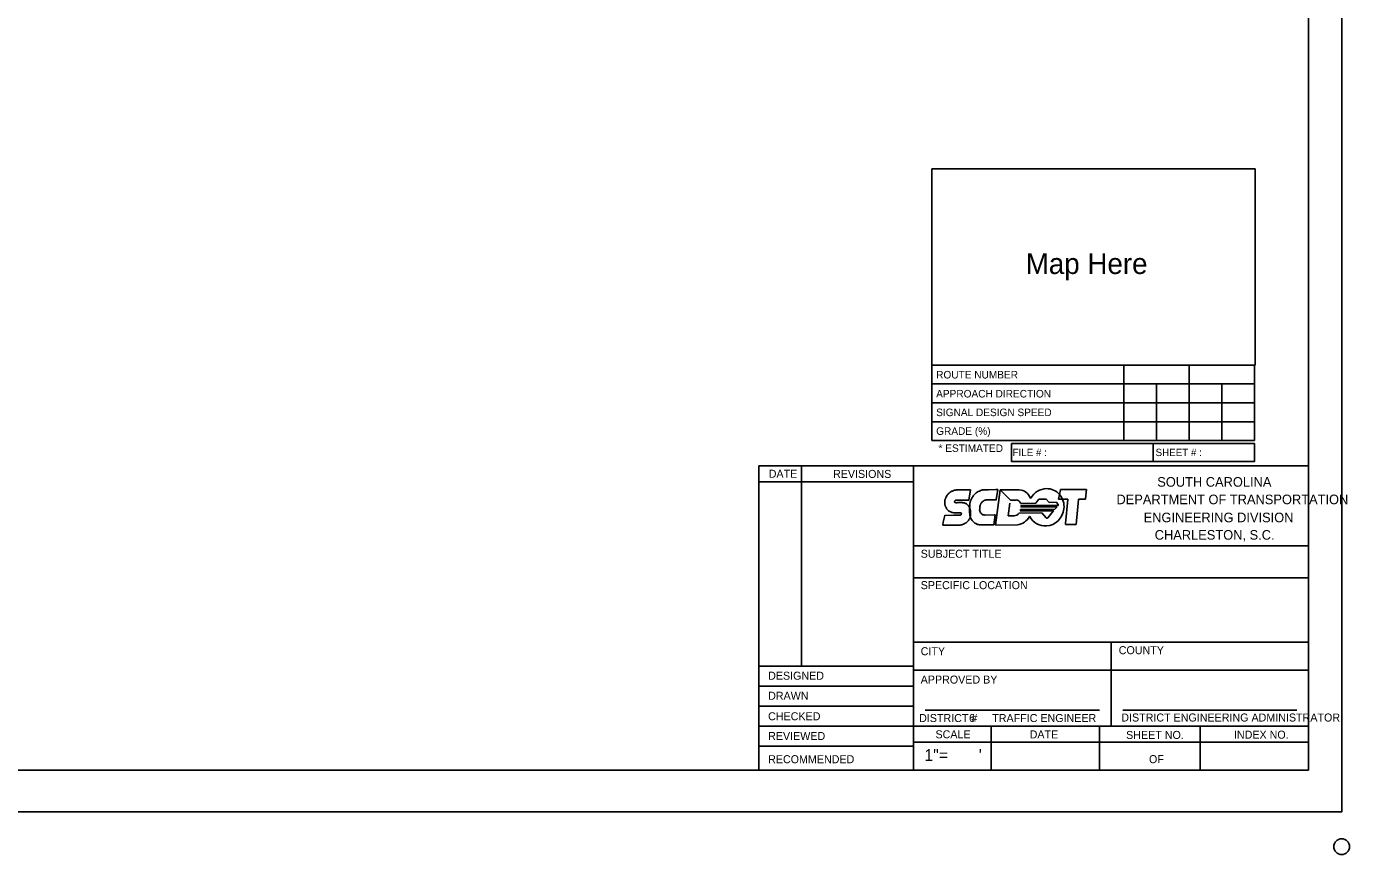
# Model space of a CAD drawing. Extents: x 0 to 3.01, y -0.05 to 1.83.
# Drawn here: x 1.504 to 3.009, y -0.048 to 0.892 of the extents above; entities that cross this region are included whole.
import ezdxf

# ---------------------------------------------------------------- set-up
doc = ezdxf.new("R2010")
doc.units = 0
doc.layers.add('RD_SHT_IplotShp', color=7, linetype='Continuous')
doc.layers.add('TR_TS_Border', color=7, linetype='Continuous')

msp = doc.modelspace()

# ---------------------------------------------------------------- linework, layer by layer
at = {"layer": 'RD_SHT_IplotShp'}
msp.add_lwpolyline([(0, 0), (3, 0), (3, 1.8333), (0, 1.8333)], close=True, dxfattribs=at)
at = {"layer": 'TR_TS_Border'}
for p, q in [((3, 0), (3, 1.8333)), ((2.9623, 0.0475), (2.9623, 1.7754)), ((2.5341, 0.5078), (2.9009, 0.5078)), ((2.5341, 0.422), (2.5341, 0.5078)), ((2.7521, 0.422), (2.7521, 0.5078)), ((2.8265, 0.422), (2.8265, 0.5078)), ((2.9009, 0.422), (2.9009, 0.5078)), ((2.5341, 0.4863), (2.9009, 0.4863)), ((2.7893, 0.422), (2.7893, 0.4863)), ((2.8637, 0.422), (2.8637, 0.4863)), ((2.5341, 0.4649), (2.9009, 0.4649)), ((2.5341, 0.4434), (2.9009, 0.4434)), ((2.5341, 0.422), (2.9009, 0.422)), ((2.7856, 0.4186), (2.7856, 0.3983)), ((2.3372, 0.3932), (2.9623, 0.3932)), ((2.3372, 0.0475), (2.3372, 0.3932)), ((2.3856, 0.3932), (2.3856, 0.1657)), ((2.5133, 0.0475), (2.5133, 0.3932)), ((2.3372, 0.375), (2.5133, 0.375)), ((2.6065, 0.3259), (2.6116, 0.3661)), ((2.6233, 0.3544), (2.6116, 0.3661)), ((2.6116, 0.3661), (2.6334, 0.366)), ((2.6116, 0.3661), (2.6233, 0.3544)), ((2.6802, 0.3659), (2.678, 0.3555)), ((2.6803, 0.3663), (2.6802, 0.3659)), ((2.6809, 0.3664), (2.6804, 0.3664)), ((2.7089, 0.3665), (2.6809, 0.3664)), ((2.7086, 0.3556), (2.7099, 0.3665)), ((2.7096, 0.3665), (2.7089, 0.3665)), ((2.7099, 0.3665), (2.7096, 0.3665)), ((2.6227, 0.3509), (2.6206, 0.3364)), ((2.6298, 0.3544), (2.6233, 0.3544)), ((2.6522, 0.3507), (2.6349, 0.3506)), ((2.6353, 0.348), (2.677, 0.3483)), ((2.6758, 0.3466), (2.6353, 0.3464)), ((2.6557, 0.3554), (2.6522, 0.3507)), ((2.6638, 0.3554), (2.6557, 0.3554)), ((2.6674, 0.3517), (2.6638, 0.3554)), ((2.6753, 0.3518), (2.6674, 0.3517)), ((2.6739, 0.3439), (2.676, 0.3463)), ((2.6757, 0.3517), (2.6777, 0.3493)), ((2.6757, 0.3517), (2.6777, 0.3493)), ((2.6777, 0.3493), (2.6757, 0.3517)), ((2.677, 0.3483), (2.6771, 0.3478)), ((2.6771, 0.3478), (2.6772, 0.3477)), ((2.6772, 0.3477), (2.6777, 0.3487)), ((2.678, 0.3555), (2.6882, 0.3554)), ((2.6886, 0.3549), (2.686, 0.3278)), ((2.6982, 0.3265), (2.7008, 0.3549)), ((2.7012, 0.3554), (2.7083, 0.3554)), ((2.6206, 0.3364), (2.6274, 0.3366)), ((2.633, 0.3395), (2.659, 0.3397)), ((2.672, 0.3422), (2.6345, 0.342)), ((2.6349, 0.3437), (2.6739, 0.3439)), ((2.659, 0.3397), (2.6641, 0.3342)), ((2.6659, 0.3342), (2.6721, 0.3418)), ((2.6313, 0.3261), (2.6065, 0.3259)), ((2.686, 0.3278), (2.686, 0.327)), ((2.6863, 0.3265), (2.6982, 0.3265)), ((2.9623, 0.3022), (2.5133, 0.3022)), ((2.9623, 0.2658), (2.5133, 0.2658)), ((2.9623, 0.193), (2.5133, 0.193)), ((2.7378, 0.193), (2.7378, 0.0975)), ((2.3372, 0.1657), (2.5133, 0.1657)), ((2.9623, 0.1612), (2.5133, 0.1612)), ((2.3372, 0.143), (2.5133, 0.143)), ((2.3372, 0.1203), (2.5133, 0.1203)), ((2.5265, 0.1157), (2.7246, 0.1157)), ((2.9491, 0.1157), (2.751, 0.1157)), ((2.9623, 0.0975), (2.3372, 0.0975)), ((2.6013, 0.0475), (2.6013, 0.0975)), ((2.7246, 0.0475), (2.7246, 0.0975)), ((2.8391, 0.0475), (2.8391, 0.0975)), ((2.9623, 0.0793), (2.5133, 0.0793)), ((2.3372, 0.0748), (2.5133, 0.0748)), ((0.1686, 0.0475), (2.9623, 0.0475)), ((0.0238, 0), (3, 0))]:
    msp.add_line(p, q, dxfattribs=at)
for points in [[(2.5341, 0.5078), (2.9015, 0.5078), (2.9015, 0.7306), (2.5341, 0.7306)], [(2.6244, 0.4186), (2.9009, 0.4186), (2.9009, 0.3983), (2.6244, 0.3983)]]:
    msp.add_lwpolyline(points, close=True, dxfattribs=at)
for points in [[(2.5561, 0.3406), (2.5554, 0.341), (2.5545, 0.3413), (2.5537, 0.3417), (2.553, 0.3422), (2.5523, 0.3428), (2.5517, 0.3434), (2.5512, 0.3438), (2.5507, 0.3445), (2.5505, 0.3452), (2.5501, 0.3459), (2.5496, 0.3466), (2.5494, 0.3473), (2.5491, 0.3479), (2.549, 0.3485), (2.5489, 0.3491), (2.5488, 0.3495), (2.5488, 0.3502), (2.5488, 0.3515), (2.5488, 0.3522), (2.5488, 0.3533), (2.5489, 0.3542), (2.549, 0.3549), (2.5493, 0.3558), (2.5497, 0.3566), (2.55, 0.3574), (2.5505, 0.3583), (2.5507, 0.3589), (2.5513, 0.3599), (2.552, 0.3606), (2.5527, 0.3615), (2.5535, 0.3623), (2.5542, 0.3627), (2.555, 0.3634), (2.5561, 0.364), (2.5566, 0.3643), (2.5575, 0.3646), (2.5581, 0.3649), (2.5587, 0.3652), (2.5596, 0.3655), (2.5605, 0.3656), (2.5613, 0.3657), (2.5621, 0.3658), (2.5627, 0.3658), (2.5634, 0.3658), (2.5725, 0.3659), (2.5778, 0.3659)], [(2.5778, 0.3659), (2.5759, 0.3543), (2.562, 0.3543), (2.5616, 0.3542), (2.561, 0.3541), (2.5608, 0.3539), (2.5605, 0.3537), (2.5602, 0.3535), (2.5601, 0.3534), (2.5601, 0.3532), (2.56, 0.3529), (2.5599, 0.3526), (2.5599, 0.3524), (2.5599, 0.3521), (2.56, 0.3521), (2.5601, 0.3517), (2.5602, 0.3516), (2.5604, 0.3515), (2.5608, 0.3514), (2.5609, 0.3514), (2.5614, 0.3513), (2.5624, 0.3513), (2.5634, 0.3514), (2.5641, 0.3514), (2.565, 0.3515), (2.5676, 0.3515)], [(2.5774, 0.3517), (2.5773, 0.3509), (2.5771, 0.35), (2.577, 0.3488), (2.577, 0.348), (2.577, 0.3471), (2.577, 0.3468), (2.5769, 0.3464), (2.5769, 0.3462), (2.5768, 0.3458), (2.5768, 0.3453), (2.5768, 0.345), (2.5767, 0.3446), (2.5767, 0.344), (2.5767, 0.3435), (2.5767, 0.3431), (2.5767, 0.3426), (2.5767, 0.3423), (2.5767, 0.3419), (2.5767, 0.3413), (2.5768, 0.3405), (2.5769, 0.3397), (2.577, 0.339), (2.577, 0.3383), (2.5771, 0.3375), (2.5773, 0.337), (2.5773, 0.3364), (2.5774, 0.3359), (2.5777, 0.3352), (2.5778, 0.3345), (2.5779, 0.3341), (2.5785, 0.3332), (2.579, 0.3324), (2.5793, 0.3318), (2.5798, 0.3312), (2.5803, 0.3306), (2.581, 0.3299), (2.5816, 0.3293), (2.5822, 0.3288), (2.5829, 0.3282), (2.5839, 0.3278), (2.5847, 0.3272), (2.5853, 0.327), (2.586, 0.3267), (2.5866, 0.3266), (2.5871, 0.3264), (2.588, 0.3262), (2.5884, 0.3262), (2.5891, 0.3261), (2.5896, 0.3261), (2.6042, 0.3261), (2.6043, 0.3262), (2.6043, 0.3262), (2.6058, 0.3374), (2.6053, 0.3374), (2.5945, 0.3373), (2.5935, 0.3374), (2.5927, 0.3375), (2.592, 0.3377), (2.5913, 0.3381), (2.5907, 0.3385), (2.59, 0.3392), (2.5895, 0.3398), (2.5891, 0.3403), (2.5888, 0.341), (2.5886, 0.3416), (2.5884, 0.3422), (2.5883, 0.3431), (2.5884, 0.3442), (2.5885, 0.3452), (2.5886, 0.3464), (2.5887, 0.3472), (2.5888, 0.3483), (2.5891, 0.349), (2.5895, 0.3497), (2.5898, 0.3505), (2.5903, 0.3513), (2.591, 0.3518), (2.5916, 0.3525), (2.5922, 0.3531), (2.5932, 0.3536), (2.594, 0.3541), (2.5947, 0.3543), (2.5951, 0.3544), (2.5959, 0.3545), (2.5968, 0.3545), (2.6072, 0.3545), (2.6073, 0.3546), (2.6089, 0.3665)], [(2.6089, 0.3665), (2.6067, 0.3665), (2.5985, 0.3661), (2.5958, 0.3661), (2.5941, 0.3661), (2.593, 0.366), (2.5916, 0.3658), (2.5907, 0.3656), (2.5899, 0.3654), (2.5889, 0.3649), (2.588, 0.3645), (2.5868, 0.364), (2.5857, 0.3633), (2.5845, 0.3624), (2.5841, 0.3621), (2.5834, 0.3615), (2.5825, 0.3608), (2.5818, 0.36), (2.581, 0.359), (2.5805, 0.3581), (2.5799, 0.3573), (2.5795, 0.3566), (2.5791, 0.3558), (2.5787, 0.355), (2.5782, 0.3541), (2.5779, 0.3533), (2.5777, 0.3524), (2.5774, 0.3517)], [(2.5767, 0.3466), (2.5769, 0.3462), (2.577, 0.3458), (2.5771, 0.3454), (2.5771, 0.3452), (2.5773, 0.3448), (2.5774, 0.3443), (2.5775, 0.344), (2.5775, 0.3438), (2.5776, 0.3435), (2.5777, 0.3433), (2.5777, 0.3431), (2.5777, 0.3429), (2.5778, 0.3427), (2.5778, 0.3423), (2.5778, 0.342), (2.5778, 0.3417), (2.5779, 0.3415), (2.5779, 0.3412), (2.5779, 0.341), (2.578, 0.3406), (2.578, 0.3403), (2.578, 0.3399), (2.578, 0.3396), (2.578, 0.3396), (2.578, 0.3392), (2.578, 0.3389), (2.578, 0.3385), (2.578, 0.3383), (2.578, 0.3382), (2.578, 0.338), (2.578, 0.3376), (2.578, 0.3373), (2.5779, 0.3371), (2.5779, 0.3367), (2.5779, 0.3364), (2.5778, 0.3362), (2.5778, 0.3359), (2.5778, 0.3357), (2.5777, 0.3354), (2.5776, 0.3352), (2.5776, 0.3349), (2.5775, 0.3347), (2.5774, 0.3344), (2.5773, 0.334), (2.5771, 0.3336), (2.5769, 0.3329), (2.5766, 0.3325), (2.5762, 0.3321), (2.576, 0.3318), (2.5756, 0.3313), (2.5752, 0.3307), (2.5746, 0.3301), (2.5738, 0.3292), (2.573, 0.3286), (2.5719, 0.328), (2.5708, 0.3272), (2.5699, 0.3269), (2.569, 0.3265), (2.5682, 0.3262), (2.5673, 0.3261), (2.5663, 0.3259), (2.5657, 0.3259), (2.557, 0.3257), (2.5466, 0.3257), (2.5464, 0.3259), (2.5464, 0.3259), (2.5464, 0.3261), (2.5464, 0.3262), (2.547, 0.3291), (2.5486, 0.3367), (2.5486, 0.3368), (2.5488, 0.337), (2.5488, 0.337), (2.5492, 0.3368), (2.5588, 0.337), (2.5654, 0.337), (2.5659, 0.3371), (2.5662, 0.3371), (2.5666, 0.3372), (2.567, 0.3374), (2.5672, 0.3377), (2.5674, 0.3379), (2.5675, 0.3383), (2.5676, 0.3386), (2.5676, 0.339), (2.5676, 0.3392), (2.5675, 0.3392), (2.5674, 0.3394), (2.5674, 0.3396), (2.5672, 0.3398), (2.5669, 0.3399), (2.5667, 0.34), (2.5666, 0.34), (2.5593, 0.3399), (2.559, 0.3399), (2.5587, 0.34), (2.5582, 0.34), (2.5578, 0.3402), (2.5568, 0.3403), (2.5561, 0.3406)], [(2.5676, 0.3515), (2.5684, 0.3514), (2.5692, 0.3513), (2.5699, 0.3512), (2.5708, 0.351), (2.5714, 0.3508), (2.572, 0.3505), (2.5725, 0.3503), (2.5732, 0.3499), (2.574, 0.3494), (2.5745, 0.349), (2.575, 0.3487), (2.5754, 0.3483), (2.5759, 0.3476), (2.5762, 0.3473), (2.5766, 0.3468), (2.5767, 0.3466)]]:
    msp.add_lwpolyline(points, dxfattribs=at)
msp.add_circle((3, -0.0395), 0.00894, dxfattribs=at)
for centre, major_axis, start_param, end_param in [((2.6326, 0.3507), (0, 0.0153), 5.101309, 6.228759), ((2.6647, 0.3449), (0, 0.0224), 0.022191, 1.026566), ((2.6648, 0.3468), (0, 0.0205), 4.590524, 6.310821), ((2.6804, 0.3662), (0, 0.000124), 0, 1.322539), ((2.6301, 0.3493), (0, 0.0052), 4.972804, 6.356492), ((2.6232, 0.3471), (0, 0.0128), 4.666228, 4.78426), ((2.6463, 0.3566), (0, 0.000247), 1.959716, 4.168159), ((2.6753, 0.3513), (0, 0.000494), 5.415198, 6.296193), ((2.6759, 0.3465), (0, 0.000185), 3.986308, 6.285649), ((2.6773, 0.3489), (0, -0.000494), 1.075193, 2.27985), ((2.6882, 0.3549), (0, -0.000494), 1.467405, 3.132152), ((2.7012, 0.3548), (0, 0.000494), 0, 1.477178), ((2.7083, 0.3557), (0, -0.000371), 0, 1.445107), ((2.6275, 0.3439), (0, -0.00733), 6.271457, 7.213216), ((2.6283, 0.347), (0, -0.0211), 0.151273, 0.993651), ((2.6231, 0.3471), (0, -0.0129), 1.163643, 1.303168), ((2.6453, 0.3353), (0, -0.000247), 2.058368, 4.135244), ((2.6622, 0.3448), (0, -0.0199), 5.19996, 6.392752), ((2.665, 0.335), (0, -0.00124), 5.487728, 7.137097), ((2.6633, 0.347), (0, -0.022), 0.045208, 1.450715), ((2.672, 0.342), (0, 0.000247), 3.995698, 6.287734), ((2.6863, 0.3269), (0, -0.000371), 4.712389, 6.283185)]:
    msp.add_ellipse(centre, major_axis=major_axis, ratio=0.950042, start_param=start_param, end_param=end_param, dxfattribs=at)

# ---------------------------------------------------------------- texts
for s, height, p in [('Map Here', 0.02359, (2.6407, 0.6112)), ('ROUTE NUMBER', 0.008578, (2.5389, 0.4925)), ('APPROACH DIRECTION', 0.008578, (2.5389, 0.4709)), ('SIGNAL DESIGN SPEED', 0.008578, (2.5389, 0.4497)), ('GRADE (%)', 0.00858, (2.5389, 0.4284)), ('* ESTIMATED', 0.008578, (2.5416, 0.409)), ('FILE # :', 0.00833, (2.6258, 0.4043)), ('SHEET # :', 0.00833, (2.7884, 0.4043)), ('DATE', 0.0091, (2.3485, 0.3797)), ('REVISIONS', 0.0091, (2.4216, 0.3795)), ('SOUTH CAROLINA', 0.010918, (2.7903, 0.3695)), ('DEPARTMENT OF TRANSPORTATION', 0.010918, (2.7439, 0.3496)), ('ENGINEERING DIVISION', 0.010918, (2.7748, 0.3291)), ('CHARLESTON, S.C.', 0.010918, (2.7874, 0.3093)), ('SUBJECT TITLE', 0.009098, (2.5213, 0.2888)), ('SPECIFIC LOCATION', 0.009098, (2.5213, 0.2531)), ('CITY', 0.0091, (2.5213, 0.178)), ('COUNTY', 0.0091, (2.7465, 0.1792)), ('DESIGNED', 0.0091, (2.3478, 0.1502)), ('APPROVED BY', 0.009098, (2.5213, 0.1458)), ('APPROVED BY', 0.009098, (2.5213, 0.1458)), ('DRAWN', 0.0091, (2.3478, 0.1274)), ('CHECKED', 0.0091, (2.3478, 0.1041)), ('DISTRICT #     TRAFFIC ENGINEER', 0.009098, (2.5195, 0.1021)), ('6', 0.0091, (2.5763, 0.1022)), ('DISTRICT ENGINEERING ADMINISTRATOR', 0.009098, (2.7494, 0.1027)), ('REVIEWED', 0.0091, (2.3478, 0.0817)), ('SCALE', 0.0091, (2.5381, 0.0836)), ('DATE', 0.0091, (2.6452, 0.0835)), ('SHEET NO.', 0.0091, (2.7549, 0.0829)), ('INDEX NO.', 0.0091, (2.8775, 0.0832)), ('RECOMMENDED', 0.009098, (2.3478, 0.0553)), ('1"=       \'', 0.013434, (2.5255, 0.0579)), ('OF', 0.0091, (2.7809, 0.0554))]:
    msp.add_text(s, height=height, dxfattribs=at).set_placement(p)

doc.saveas('drawing.dxf')
